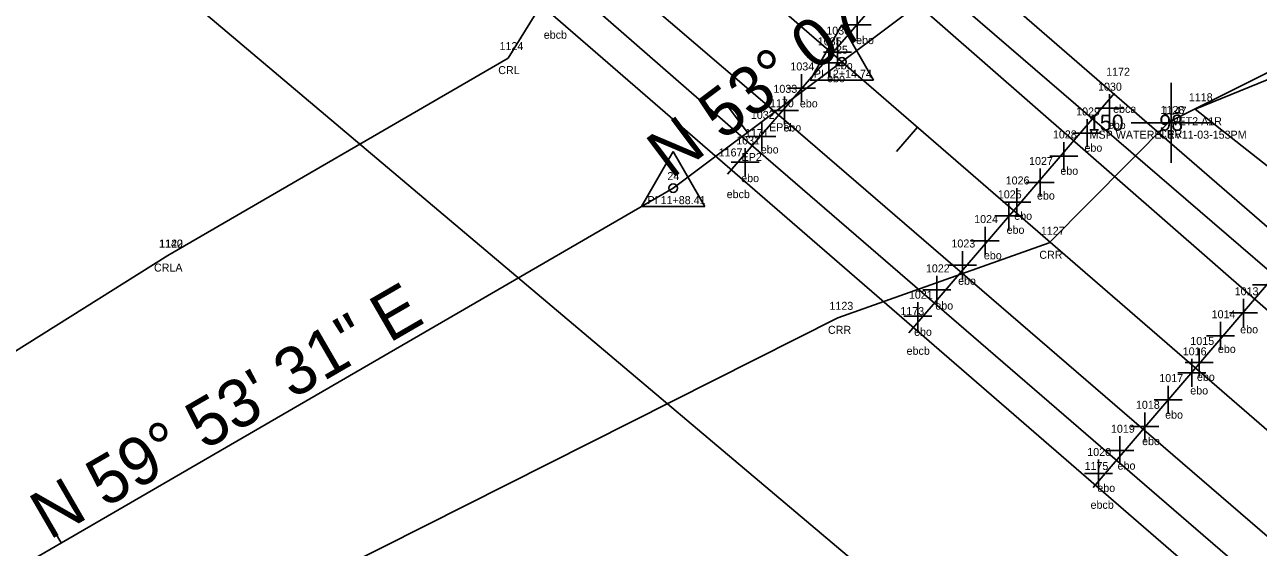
# Model space of a CAD drawing. Extents: x 2085293 to 2087464, y 876528 to 879458.
# Drawn here: x 2086332.2 to 2086486.4, y 878449.4 to 878514.7 of the extents above; entities that cross this region are included whole.
import ezdxf

# ---------------------------------------------------------------- set-up
doc = ezdxf.new("R2010")
doc.units = 0
for name, color, linetype in [('RD_EX_Bridge', 7, 'Continuous'), ('RD_EX_H2O', 7, 'Continuous'), ('RD_EX_H2O_txCode', 7, 'Continuous'), ('RD_EX_H2O_WetLd', 7, 'Continuous'), ('RD_EX_H2O_WetLd_txCode', 7, 'Continuous'), ('RD_EX_Misc', 7, 'Continuous'), ('RD_EX_Misc_txCode', 7, 'Continuous'), ('RD_EX_Road', 7, 'Continuous'), ('RD_EX_Road_txCode', 7, 'Continuous'), ('RD_EX_VEG', 7, 'Continuous'), ('RD_HC_Cl', 7, 'Continuous'), ('RD_HC_Data', 7, 'Continuous'), ('RD_HC_Data_Tic', 7, 'Continuous'), ('RD_HC_txCode', 7, 'Continuous'), ('RD_SMD_Locator', 7, 'Continuous')]:
    doc.layers.add(name, color=color, linetype=linetype)

msp = doc.modelspace()

# ---------------------------------------------------------------- linework, layer by layer
at = {"layer": 'RD_EX_Bridge'}
msp.add_lwpolyline([(2086377.74, 878584.61), (2086559.01, 878427.4), (2086533.93, 878398.26), (2086352.47, 878555.51), (2086377.74, 878584.61)], dxfattribs=at)
at = {"layer": 'RD_EX_H2O'}
for points in [[(2086350.1, 878485.82), (2086392.62, 878510.5), (2086406.71, 878533.27), (2086442.18, 878554.15), (2086494.98, 878562.84), (2086530.51, 878595.43), (2086576.04, 878629.72), (2086651.92, 878628.48)], [(2086371.86, 878446.8), (2086433.83, 878478.04), (2086460.24, 878487.42), (2086475.2, 878502.52), (2086538.58, 878534.3), (2086576.08, 878553.56), (2086644.41, 878579.03)], [(2086350.1, 878485.82), (2086285.47, 878445.27), (2086265.5, 878388.73), (2086266.53, 878366.23)]]:
    msp.add_lwpolyline(points, dxfattribs=at)
at = {"layer": 'RD_EX_H2O_WetLd'}
msp.add_lwpolyline([(2086539.89, 878455.74), (2086478.45, 878504.11), (2086517.42, 878520.02), (2086545.81, 878533.58), (2086576.08, 878553.56)], dxfattribs=at)
at = {"layer": 'RD_EX_Misc'}
for p, q in [((2086445.86, 878525.9), (2086420.02, 878496.01)), ((2086436.22, 878516.39), (2086436.22, 878512.89)), ((2086437.97, 878514.64), (2086434.47, 878514.64)), ((2086433.78, 878512.98), (2086433.78, 878509.48)), ((2086435.53, 878511.23), (2086432.03, 878511.23)), ((2086432.7, 878511.65), (2086432.7, 878508.15)), ((2086434.45, 878509.9), (2086430.95, 878509.9)), ((2086429.28, 878508.51), (2086429.28, 878505.01)), ((2086475.48, 878497.43), (2086475.48, 878507.43)), ((2086431.03, 878506.76), (2086427.53, 878506.76)), ((2086468.4, 878506.1), (2086442.69, 878476.18)), ((2086467.76, 878505.98), (2086467.76, 878502.48)), ((2086427.16, 878505.71), (2086427.16, 878502.21)), ((2086428.91, 878503.96), (2086425.41, 878503.96)), ((2086464.98, 878502.88), (2086464.98, 878499.38)), ((2086469.51, 878504.23), (2086466.01, 878504.23)), ((2086424.34, 878502.45), (2086424.34, 878498.95)), ((2086470.48, 878502.43), (2086480.48, 878502.43)), ((2086426.09, 878500.7), (2086422.59, 878500.7)), ((2086462.07, 878500.01), (2086462.07, 878496.51)), ((2086466.73, 878501.13), (2086463.23, 878501.13)), ((2086422.23, 878499.26), (2086422.23, 878495.76)), ((2086463.82, 878498.26), (2086460.32, 878498.26)), ((2086423.98, 878497.51), (2086420.48, 878497.51)), ((2086459.1, 878496.69), (2086459.1, 878493.19)), ((2086456.2, 878494.26), (2086456.2, 878490.76)), ((2086460.85, 878494.94), (2086457.35, 878494.94)), ((2086457.95, 878492.51), (2086454.45, 878492.51)), ((2086455.2, 878492.52), (2086455.2, 878489.02)), ((2086456.95, 878490.77), (2086453.45, 878490.77)), ((2086452.23, 878489.43), (2086452.23, 878485.93)), ((2086453.98, 878487.68), (2086450.48, 878487.68)), ((2086449.39, 878486.38), (2086449.39, 878482.88)), ((2086491.28, 878486.71), (2086465.7, 878456.82)), ((2086451.14, 878484.63), (2086447.64, 878484.63)), ((2086446.2, 878483.27), (2086446.2, 878479.77)), ((2086447.95, 878481.52), (2086444.45, 878481.52)), ((2086489.14, 878482.16), (2086485.64, 878482.16)), ((2086443.8, 878479.98), (2086443.8, 878476.48)), ((2086484.5, 878480.41), (2086484.5, 878476.91)), ((2086445.55, 878478.23), (2086442.05, 878478.23)), ((2086486.25, 878478.66), (2086482.75, 878478.66)), ((2086481.63, 878477.54), (2086481.63, 878474.04)), ((2086483.38, 878475.79), (2086479.88, 878475.79)), ((2086478.96, 878474.2), (2086478.96, 878470.7)), ((2086480.71, 878472.45), (2086477.21, 878472.45)), ((2086478.03, 878472.9), (2086478.03, 878469.4)), ((2086479.78, 878471.15), (2086476.28, 878471.15)), ((2086475.08, 878469.56), (2086475.08, 878466.06)), ((2086476.83, 878467.81), (2086473.33, 878467.81)), ((2086472.16, 878466.22), (2086472.16, 878462.72)), ((2086473.91, 878464.47), (2086470.41, 878464.47)), ((2086469.05, 878463.23), (2086469.05, 878459.73)), ((2086470.8, 878461.48), (2086467.3, 878461.48)), ((2086466.4, 878460.32), (2086466.4, 878456.82)), ((2086468.15, 878458.57), (2086464.65, 878458.57))]:
    msp.add_line(p, q, dxfattribs=at)
at = {"layer": 'RD_EX_Road'}
for points in [[(2086372.48, 878578.63), (2086375.14, 878581.18), (2086443.25, 878522.25), (2086511.37, 878463.55), (2086556.66, 878424.84), (2086553.57, 878421.17)], [(2086372.48, 878578.63), (2086440.93, 878519.74), (2086508.75, 878460.4), (2086553.57, 878421.17), (2086626.32, 878357.37), (2086700.27, 878293.03), (2086782.28, 878221.68)], [(2086358.19, 878561.82), (2086355.45, 878558.6), (2086422.99, 878499.64), (2086491.68, 878440.33), (2086536.87, 878401.71), (2086539.89, 878405.13)], [(2086358.19, 878561.82), (2086426.45, 878503.36), (2086494.99, 878444.26), (2086539.89, 878405.13), (2086612.82, 878341.2), (2086686.27, 878277.41), (2086769.9, 878205.27), (2086844.45, 878140.34), (2086932.82, 878063.42), (2086964.75, 878034.46), (2087001.42, 877999.16), (2087042.78, 877955.43), (2087078.39, 877914.63), (2087110.34, 877876.43), (2087140.35, 877836.91), (2087173.38, 877789.29), (2087206.69, 877736.44), (2087236.08, 877683.18), (2087259.17, 877638.22), (2087287.12, 877578.12)]]:
    msp.add_lwpolyline(points, dxfattribs=at)
at = {"layer": 'RD_EX_VEG'}
msp.add_lwpolyline([(2086498.28, 878394.88), (2086329.73, 878537.22), (2086212.13, 878664.14), (2086102.42, 878763.92), (2085939.19, 878906.04), (2085793.62, 879021.84)], dxfattribs=at)
at = {"layer": 'RD_HC_Cl'}
for p, q in [((2086923.31, 878086.15), (2085624.78, 879211.84)), ((2086413.25, 878494.25), (2086458.69, 878528.33)), ((2086306.79, 878432.52), (2086413.25, 878494.25))]:
    msp.add_line(p, q, dxfattribs=at)
at = {"layer": 'RD_HC_Data'}
for p, q in [((2086430.35, 878507.76), (2086434.32, 878514.64)), ((2086434.32, 878514.64), (2086438.29, 878507.76)), ((2086430.35, 878507.76), (2086438.29, 878507.76)), ((2086409.28, 878491.96), (2086413.25, 878498.84)), ((2086413.25, 878498.84), (2086417.22, 878491.96)), ((2086409.28, 878491.96), (2086417.22, 878491.96))]:
    msp.add_line(p, q, dxfattribs=at)
for centre in [(2086434.32, 878510.05), (2086413.25, 878494.25)]:
    msp.add_circle(centre, 0.529, dxfattribs=at)
at = {"layer": 'RD_HC_Data_Tic'}
for p, q in [((2086422.53, 878501.21), (2086420.13, 878504.41)), ((2086443.76, 878501.86), (2086441.14, 878498.84)), ((2086336.77, 878449.9), (2086334.77, 878453.36))]:
    msp.add_line(p, q, dxfattribs=at)
at = {"layer": 'RD_SMD_Locator'}
for centre in [(2086392.62, 878510.5), (2086434.32, 878510.05), (2086426.45, 878503.36), (2086478.45, 878504.11), (2086475.2, 878502.52), (2086422.99, 878499.64), (2086413.25, 878494.25), (2086460.24, 878487.42), (2086350.1, 878485.82), (2086350.1, 878485.82), (2086433.83, 878478.04)]:
    msp.add_circle(centre, 0.001, dxfattribs=at)

# ---------------------------------------------------------------- texts
at = {"layer": 'RD_EX_H2O_txCode'}
for s, p in [('1124', (2086391.55, 878511.5)), ('CRL', (2086391.39, 878508.5)), ('1128', (2086474.14, 878503.52)), ('CRR', (2086473.95, 878500.52)), ('1127', (2086459.18, 878488.42)), ('1140', (2086349, 878486.82)), ('1122', (2086349.04, 878486.82)), ('CRR', (2086458.99, 878485.42)), ('CRLA', (2086348.38, 878483.82)), ('CRLA', (2086348.38, 878483.82)), ('1123', (2086432.77, 878479.04)), ('CRR', (2086432.58, 878476.04))]:
    msp.add_text(s, height=1, dxfattribs=at).set_placement(p)
at = {"layer": 'RD_EX_H2O_WetLd_txCode'}
for s, p in [('1118', (2086477.67, 878505.11)), ('WET2 A1R', (2086475.12, 878502.11))]:
    msp.add_text(s, height=1, dxfattribs=at).set_placement(p)
at = {"layer": 'RD_EX_Misc_txCode'}
for s, height, p in [('ebcb', 1, (2086397.08, 878512.92)), ('1036', 1, (2086432.37, 878513.43)), ('1035', 1, (2086431.31, 878512.1)), ('ebo', 1, (2086436.1, 878512.25)), ('1034', 1, (2086427.89, 878508.96)), ('ebo', 1, (2086433.44, 878509.1)), ('1172', 1, (2086467.34, 878508.3)), ('ebo', 1, (2086432.48, 878507.49)), ('1030', 1, (2086466.33, 878506.43)), ('1033', 1, (2086425.77, 878506.16)), ('ebo', 1, (2086429.07, 878504.34)), ('1029', 1, (2086463.59, 878503.33)), ('ebca', 1, (2086468.21, 878503.66)), ('1147', 1, (2086474.42, 878503.43)), ('1032', 1, (2086422.95, 878502.9)), ('150      98 ', 2, (2086465.06, 878501.43)), ('ebo', 1, (2086427.02, 878501.33)), ('1028', 1, (2086460.69, 878500.46)), ('MSP WATERELEV11-03-153PM', 1, (2086465.27, 878500.43)), ('ebo', 1, (2086467.55, 878501.64)), ('1031', 1, (2086421.12, 878499.71)), ('ebo', 1, (2086464.63, 878498.8)), ('1167', 1, (2086418.93, 878498.21)), ('ebo', 1, (2086424.19, 878498.58)), ('1027', 1, (2086457.71, 878497.14)), ('ebo', 1, (2086461.62, 878495.92)), ('ebo', 1, (2086421.74, 878495)), ('1026', 1, (2086454.79, 878494.71)), ('ebcb', 1, (2086419.93, 878493)), ('1025', 1, (2086453.81, 878492.97)), ('ebo', 1, (2086458.7, 878492.82)), ('1024', 1, (2086450.85, 878489.88)), ('ebo', 1, (2086455.86, 878490.29)), ('ebo', 1, (2086454.9, 878488.54)), ('1023', 1, (2086448.01, 878486.83)), ('ebo', 1, (2086452.06, 878485.35)), ('1022', 1, (2086444.82, 878483.72)), ('ebo', 1, (2086448.84, 878482.17)), ('1021', 1, (2086442.7, 878480.43)), ('1013', 1, (2086483.4, 878480.86)), ('ebo', 1, (2086446, 878479.07)), ('1173', 1, (2086441.63, 878478.38)), ('1014', 1, (2086480.52, 878477.99)), ('ebo', 1, (2086443.34, 878475.79)), ('ebo', 1, (2086484.09, 878476.1)), ('1015', 1, (2086477.86, 878474.65)), ('ebcb', 1, (2086442.41, 878473.42)), ('1016', 1, (2086476.91, 878473.35)), ('ebo', 1, (2086481.3, 878473.65)), ('1017', 1, (2086473.98, 878470.01)), ('ebo', 1, (2086478.68, 878470.16)), ('ebo', 1, (2086477.85, 878468.46)), ('1018', 1, (2086471.06, 878466.67)), ('ebo', 1, (2086474.71, 878465.44)), ('1019', 1, (2086467.94, 878463.68)), ('ebo', 1, (2086471.83, 878462.13)), ('1020', 1, (2086464.98, 878460.77)), ('1175', 1, (2086464.64, 878459.02)), ('ebo', 1, (2086468.77, 878459.07)), ('ebo', 1, (2086466.24, 878456.28)), ('ebcb', 1, (2086465.39, 878454.17))]:
    msp.add_text(s, height=height, dxfattribs=at).set_placement(p)
at = {"layer": 'RD_EX_Road_txCode'}
for s, p in [('1170', (2086425.34, 878504.36)), ('1171', (2086422.21, 878500.64)), ('EPR', (2086425.22, 878501.36)), ('EP2', (2086421.79, 878497.64))]:
    msp.add_text(s, height=1, dxfattribs=at).set_placement(p)
at = {"layer": 'RD_HC_Data'}
for s, rotation, p in [('N 53%%d 07\' 41" E', 36.8718, (2086412.99, 878495.3)), ('N 59%%d 53\' 31" E', 30.1079, (2086335.32, 878450.22))]:
    msp.add_text(s, height=6, rotation=rotation, dxfattribs=at).set_placement(p)
at = {"layer": 'RD_HC_txCode'}
for s, p in [('25', (2086433.59, 878511.05)), ('PI 12+14.74', (2086430.82, 878508.05)), ('24', (2086412.52, 878495.25)), ('PI 11+88.41', (2086410.04, 878492.25))]:
    msp.add_text(s, height=1, dxfattribs=at).set_placement(p)

doc.saveas('drawing.dxf')
